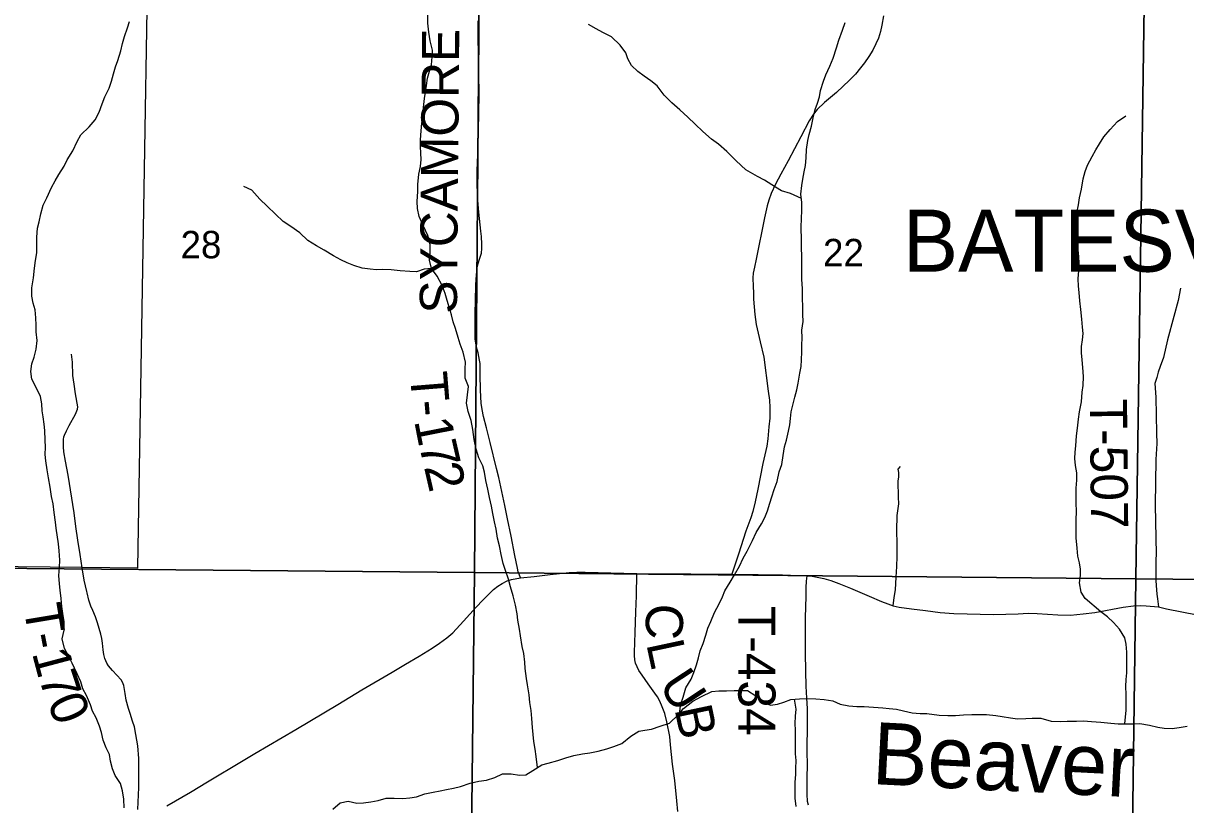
# Model space of a CAD drawing. Extents: x 0 to 191, y 0 to 55.
# Drawn here: x 185.647 to 187.422, y 51.096 to 52.289 of the extents above; entities that cross this region are included whole.
import ezdxf

# ---------------------------------------------------------------- set-up
doc = ezdxf.new("R2010")
doc.units = 0
for name, color, linetype in [('GM_X_Corporation', 7, 'Continuous'), ('GM_X_Corporation_Text', 7, 'Continuous'), ('GM_X_County_Road', 7, 'Continuous'), ('GM_X_Minor_River', 7, 'Continuous'), ('GM_X_Minor_River_Text', 7, 'Continuous'), ('GM_X_Section_Text', 7, 'Continuous'), ('GM_X_State_Route', 7, 'Continuous'), ('GM_X_Township_Road', 7, 'Continuous'), ('GM_X_Township_Road_Text', 7, 'Continuous')]:
    doc.layers.add(name, color=color, linetype=linetype)

msp = doc.modelspace()

# ---------------------------------------------------------------- linework, layer by layer
at = {"layer": 'GM_X_Corporation'}
for points in [[(184.8319, 50.3472), (184.8438, 50.7018), (184.8438, 50.7041), (184.8504, 51.1664), (184.8504, 51.1691), (184.8564, 51.468), (185.0493, 51.466), (185.0519, 51.466), (185.737, 51.4587), (185.8223, 51.4579), (185.8471, 52.9493), (185.8472, 52.953), (185.8634, 53.9305), (185.8653, 54.0182), (185.8655, 54.0321), (185.8681, 54.1568), (185.8476, 54.1564), (184.4129, 54.1665), (184.4114, 53.9192), (184.1701, 53.923), (184.1701, 49.9388)], [(184.8319, 50.3472), (184.8438, 50.7018), (184.8438, 50.7041), (184.8504, 51.1664), (184.8504, 51.1691), (184.8564, 51.468), (185.0493, 51.466), (185.0519, 51.466), (185.737, 51.4587), (185.8223, 51.4579), (185.8471, 52.9493), (185.8472, 52.953), (185.8634, 53.9305), (185.8653, 54.0182), (185.8655, 54.0321), (185.8681, 54.1568), (185.9791, 54.1551), (186.7401, 54.1422), (186.7662, 54.1447), (187.3845, 54.1319), (187.4205, 54.1315), (187.8766, 54.1257)]]:
    msp.add_lwpolyline(points, dxfattribs=at)
for points in [[(185.3319, 52.4794), (186.3443, 52.462), (186.336, 51.4505), (185.31, 51.4601)], [(186.3443, 52.462), (187.3608, 52.4557), (187.3457, 51.441), (186.336, 51.4505)], [(187.3608, 52.4557), (188.3785, 52.4395), (188.3652, 51.4321), (187.3457, 51.441)], [(186.336, 51.4505), (186.3245, 50.4222), (185.2935, 50.4401), (185.31, 51.4601)], [(187.3457, 51.441), (187.3319, 50.4112), (186.3245, 50.4222), (186.336, 51.4505)], [(188.3652, 51.4321), (188.3474, 50.3984), (187.3319, 50.4112), (187.3457, 51.441)]]:
    msp.add_lwpolyline(points, close=True, dxfattribs=at)
at = {"layer": 'GM_X_County_Road'}
msp.add_lwpolyline([(186.9603, 52.3005), (186.9582, 52.2862), (186.956, 52.2766), (186.9529, 52.2664), (186.949, 52.2576), (186.9441, 52.248), (186.9379, 52.2386), (186.9314, 52.2289), (186.9254, 52.2211), (186.9177, 52.2114), (186.9087, 52.2021), (186.8887, 52.1832), (186.8707, 52.1682), (186.8591, 52.1572), (186.8535, 52.1504), (186.8473, 52.1402), (186.8342, 52.1159), (186.8151, 52.079), (186.8038, 52.0589), (186.7955, 52.0437), (186.7888, 52.029), (186.7855, 52.0193), (186.7829, 52.0102), (186.7787, 51.992), (186.7662, 51.9291), (186.7636, 51.9166), (186.7616, 51.9076), (186.7609, 51.9007), (186.7615, 51.8875), (186.7619, 51.8774), (186.7622, 51.8679), (186.7642, 51.8447), (186.7662, 51.8294), (186.7692, 51.8161), (186.7724, 51.8026), (186.778, 51.7793), (186.7845, 51.7273), (186.7863, 51.714), (186.7869, 51.7027), (186.7868, 51.6864), (186.7856, 51.6729), (186.784, 51.6548), (186.7822, 51.6436), (186.7761, 51.6169), (186.7685, 51.5777), (186.7648, 51.5584), (186.7608, 51.5436), (186.7578, 51.5341), (186.7506, 51.5138), (186.739, 51.4787), (186.7289, 51.4482)], dxfattribs=at)
at = {"layer": 'GM_X_Minor_River'}
for points in [[(185.7142, 52.0806), (185.7229, 52.0943), (185.7297, 52.1084), (185.735, 52.1187), (185.7479, 52.1312), (185.757, 52.1415), (185.763, 52.1533), (185.7675, 52.1663), (185.7717, 52.1769), (185.7781, 52.1898), (185.7819, 52.2005), (185.7849, 52.2119), (185.7879, 52.2225), (185.7913, 52.2324), (185.7962, 52.2472), (185.7988, 52.2583), (185.8018, 52.2689), (185.8063, 52.2822), (185.8094, 52.2917)], [(186.4325, 51.1531), (186.4305, 51.1699), (186.4286, 51.1809), (186.4267, 51.1926), (186.4255, 51.2036), (186.4247, 51.2139), (186.4235, 51.2279), (186.4224, 51.2401), (186.4208, 51.2522), (186.4197, 51.264), (186.417, 51.2792), (186.4154, 51.289), (186.4135, 51.3042), (186.4131, 51.3141), (186.4115, 51.327), (186.4089, 51.3376), (186.4062, 51.3543), (186.4046, 51.3642), (186.4023, 51.3778), (186.4012, 51.3877), (186.3985, 51.401), (186.395, 51.415), (186.3912, 51.429), (186.3881, 51.4404), (186.3836, 51.4537), (186.3797, 51.4647), (186.377, 51.4783), (186.3744, 51.4916), (186.3713, 51.503), (186.369, 51.5167), (186.3667, 51.5281), (186.364, 51.5406), (186.3621, 51.552), (186.359, 51.5652), (186.3563, 51.5781), (186.3536, 51.5914), (186.3513, 51.6039), (186.3487, 51.6134), (186.3426, 51.6256), (186.3384, 51.6392), (186.3357, 51.6536), (186.3337, 51.6688), (186.331, 51.6828), (186.3265, 51.6965), (186.3241, 51.709), (186.3256, 51.7219), (186.3271, 51.7349), (186.3218, 51.7474), (186.3218, 51.7614), (186.3225, 51.7717), (186.3187, 51.7868), (186.3141, 51.7994), (186.3114, 51.8092), (186.3072, 51.8233), (186.3037, 51.8335), (186.3011, 51.8441), (186.298, 51.854), (186.2942, 51.8661), (186.2911, 51.8764), (186.2865, 51.8889), (186.2789, 51.9029), (186.2705, 51.9147), (186.2675, 51.9276), (186.2682, 51.9393), (186.2686, 51.9515), (186.2651, 51.9651), (186.2579, 51.9803), (186.2518, 51.9943), (186.2491, 52.0065), (186.2487, 52.0171), (186.2494, 52.0323), (186.2497, 52.0429), (186.2512, 52.0589), (186.2535, 52.0707), (186.2546, 52.0813), (186.2542, 52.0908), (186.2534, 52.1011), (186.2538, 52.1113), (186.2549, 52.125), (186.2556, 52.1368), (186.2575, 52.1489), (186.2582, 52.1607), (186.2597, 52.174), (186.2612, 52.1839), (186.263, 52.1941), (186.2645, 52.2052), (186.2672, 52.2162), (186.2702, 52.2257), (186.2713, 52.2378), (186.272, 52.2481), (186.2682, 52.2625), (186.2663, 52.2754), (186.2647, 52.2891), (186.2647, 52.3031)], [(186.8354, 52.0214), (186.8186, 52.0293), (186.8049, 52.0334), (186.7954, 52.0387), (186.7791, 52.0496), (186.7681, 52.0553), (186.7506, 52.0655), (186.7358, 52.0791), (186.7213, 52.0935), (186.7088, 52.1045), (186.6977, 52.1124), (186.6848, 52.1241), (186.673, 52.1351), (186.662, 52.1457), (186.6494, 52.1571), (186.6376, 52.1677), (186.6258, 52.1794), (186.6152, 52.1934), (186.6053, 52.2014), (186.595, 52.2085), (186.5855, 52.2153), (186.5756, 52.2244), (186.5703, 52.2347), (186.5669, 52.2441), (186.5585, 52.2559), (186.5452, 52.2684), (186.5319, 52.2752), (186.522, 52.2808), (186.5102, 52.2873)], [(186.6489, 51.2357), (186.6512, 51.2503), (186.6546, 51.2606), (186.6587, 51.2747), (186.667, 51.288), (186.6708, 51.2982), (186.6749, 51.31), (186.678, 51.3207), (186.6806, 51.3313), (186.6851, 51.3423), (186.6893, 51.3549), (186.6923, 51.3659), (186.6968, 51.3762), (186.7025, 51.3898), (186.7096, 51.4031), (186.7145, 51.4134), (186.7183, 51.4229), (186.7263, 51.4362), (186.7331, 51.4473), (186.7406, 51.4602), (186.7463, 51.4728), (186.7523, 51.4834), (186.7603, 51.4994), (186.7659, 51.5119), (186.7742, 51.5252), (186.7792, 51.5347), (186.7833, 51.545), (186.7871, 51.5564), (186.7901, 51.5663), (186.7935, 51.5773), (186.798, 51.5895), (186.8014, 51.6043), (186.8052, 51.6157), (186.8074, 51.6294), (186.8093, 51.6427), (186.8123, 51.6526), (186.8157, 51.6666), (186.8175, 51.6761), (186.8183, 51.6856), (186.8198, 51.6959), (186.822, 51.7061), (186.8254, 51.7183), (186.828, 51.7297), (186.8303, 51.7399), (186.8329, 51.7548), (186.8348, 51.7654), (186.8351, 51.7753), (186.8359, 51.7874), (186.8358, 51.7977), (186.8362, 51.8091), (186.8358, 51.8208), (186.8377, 51.8338), (186.8376, 51.8444), (186.8372, 51.8573), (186.8368, 51.8687), (186.8368, 51.8835), (186.836, 51.8983), (186.8356, 51.912), (186.8359, 51.9219), (186.8359, 51.9336), (186.8355, 51.9462), (186.8351, 51.9575), (186.835, 51.9784), (186.8354, 51.9906), (186.8357, 52.0039), (186.8361, 52.0157), (186.8345, 52.0282), (186.8356, 52.0415), (186.8375, 52.051), (186.8394, 52.0624), (186.8416, 52.0719), (186.8424, 52.0836), (186.8431, 52.0962), (186.845, 52.1099), (186.8468, 52.1194), (186.8506, 52.1319), (186.8532, 52.1448), (186.8562, 52.1574), (186.86, 52.1673), (186.8626, 52.1768), (186.8645, 52.1863), (186.869, 52.2007), (186.8724, 52.2102), (186.8785, 52.2235), (186.8838, 52.2357), (186.8886, 52.2517), (186.8924, 52.2631), (186.8981, 52.2783), (186.9018, 52.2901)], [(187.3292, 51.2196), (187.3312, 51.2408), (187.3312, 51.2647), (187.3307, 51.2769), (187.3311, 51.2875), (187.3318, 51.2977), (187.3318, 51.3088), (187.3322, 51.3194), (187.3321, 51.3293), (187.331, 51.3414), (187.3291, 51.3509), (187.3211, 51.3641), (187.3119, 51.3744), (187.3024, 51.3831), (187.2925, 51.3906), (187.2682, 51.4111), (187.2625, 51.4205), (187.2598, 51.4349), (187.2613, 51.446), (187.2613, 51.4558), (187.2597, 51.4653), (187.2571, 51.4756), (187.2563, 51.4877), (187.2547, 51.5036), (187.2547, 51.531), (187.255, 51.5439), (187.2546, 51.5572), (187.2546, 51.5686), (187.2549, 51.5796), (187.2556, 51.5917), (187.2556, 51.6031), (187.2537, 51.6141), (187.2529, 51.6248), (187.2533, 51.6346), (187.254, 51.6441), (187.2551, 51.6593), (187.2566, 51.6711), (187.2581, 51.6848), (187.26, 51.6958), (187.2626, 51.7114), (187.2641, 51.7258), (187.2652, 51.7364), (187.2659, 51.7501), (187.2647, 51.7638), (187.264, 51.7755), (187.2628, 51.7862), (187.2628, 51.7956), (187.2646, 51.8059), (187.2654, 51.8154), (187.2646, 51.8253), (187.2634, 51.8374), (187.2619, 51.8522), (187.2603, 51.8655), (187.2592, 51.878), (187.2584, 51.8879), (187.2576, 51.8989), (187.2587, 51.9118), (187.2594, 51.9225), (187.2586, 51.9331), (187.2575, 51.9426), (187.2563, 51.9547), (187.2548, 51.9676), (187.2536, 51.9786), (187.254, 51.9893), (187.2555, 51.9995), (187.2581, 52.0117), (187.2599, 52.0227), (187.2626, 52.036), (187.2656, 52.0516), (187.2686, 52.0626), (187.272, 52.0725), (187.2792, 52.0858), (187.2848, 52.0957), (187.2901, 52.1052), (187.2969, 52.1155), (187.3064, 52.1269), (187.3177, 52.1391), (187.3306, 52.1479)], [(185.8012, 51.0914), (185.8007, 51.1047), (185.7988, 51.1176), (185.7958, 51.1286), (185.7874, 51.1411), (185.7832, 51.1509), (185.7805, 51.1627), (185.7786, 51.173), (185.7736, 51.1832), (185.769, 51.1946), (185.7664, 51.2067), (185.7637, 51.2162), (185.7583, 51.2291), (185.753, 51.2389), (185.7496, 51.2488), (185.7435, 51.2632), (185.7381, 51.2734), (185.7351, 51.2837), (185.7297, 51.2962), (185.7217, 51.3121), (185.7175, 51.3216), (185.7103, 51.3345), (185.7068, 51.3496), (185.7095, 51.3629), (185.7094, 51.3762), (185.7075, 51.3884), (185.706, 51.3986), (185.7052, 51.4111), (185.7036, 51.424), (185.7025, 51.4335), (185.7017, 51.4461), (185.7024, 51.4582), (185.7028, 51.4696), (185.702, 51.4836), (185.7008, 51.4943), (185.6974, 51.5182), (185.6962, 51.5277), (185.6946, 51.5425), (185.6927, 51.5554), (185.6904, 51.5668), (185.6881, 51.5812), (185.6858, 51.5952), (185.6839, 51.6077), (185.6816, 51.621), (185.6808, 51.6309), (185.6811, 51.6423), (185.6807, 51.6529), (185.6803, 51.6677), (185.6791, 51.6772), (185.6776, 51.6882), (185.6761, 51.6977), (185.6753, 51.708), (185.6737, 51.7193), (185.6676, 51.7322), (185.6604, 51.7459), (185.6589, 51.7573), (185.66, 51.7694), (185.6637, 51.7793), (185.6667, 51.7915), (185.6686, 51.8051), (185.6671, 51.818), (185.667, 51.8283), (185.6666, 51.8393), (185.6651, 51.8518), (185.6624, 51.8617), (185.6605, 51.8723), (185.6601, 51.8852), (185.6627, 51.9004), (185.6642, 51.9153), (185.666, 51.927), (185.6679, 51.9388), (185.6679, 51.9624), (185.669, 51.9764), (185.6712, 51.9859), (185.6738, 51.9981), (185.6776, 52.0114), (185.6829, 52.0228), (185.6901, 52.0384), (185.6957, 52.0487), (185.7014, 52.0582), (185.7097, 52.0711), (185.7142, 52.0806)], [(186.2705, 51.9147), (186.2595, 51.9135), (186.2474, 51.9096), (186.2372, 51.9104), (186.2227, 51.9111), (186.2091, 51.9129), (186.1962, 51.9133), (186.1863, 51.9129), (186.1768, 51.9136), (186.1647, 51.9151), (186.1518, 51.9192), (186.1419, 51.9233), (186.132, 51.9282), (186.1206, 51.9343), (186.1065, 51.9426), (186.0948, 51.9494), (186.0818, 51.9577), (186.0693, 51.9694), (186.0556, 51.9789), (186.0442, 51.9864), (186.0324, 51.9978), (186.0195, 52.0099), (186.0085, 52.0205), (185.9959, 52.0345), (185.9841, 52.0401)], [(186.1199, 51.0895), (186.1309, 51.0994), (186.1434, 51.1017), (186.1567, 51.0987), (186.1666, 51.0991), (186.1776, 51.1007), (186.1889, 51.1026), (186.2014, 51.1061), (186.2132, 51.1065), (186.2269, 51.1058), (186.2375, 51.1066), (186.2477, 51.1085), (186.2602, 51.1127), (186.2728, 51.1154), (186.2838, 51.1174), (186.2932, 51.1197), (186.3039, 51.1216), (186.3145, 51.1239), (186.3293, 51.1293), (186.3425, 51.1324), (186.3543, 51.1339), (186.3672, 51.1378), (186.379, 51.1435), (186.3919, 51.1432), (186.4048, 51.1413), (186.4146, 51.1417), (186.4252, 51.1486), (186.4389, 51.157), (186.4484, 51.1597), (186.4631, 51.1639), (186.4753, 51.1681), (186.4878, 51.1712), (186.5011, 51.1739), (186.5121, 51.1755), (186.525, 51.1782), (186.5379, 51.1816), (186.5489, 51.1851), (186.561, 51.1897), (186.575, 51.2011), (186.5868, 51.2084), (186.5962, 51.2103), (186.6061, 51.2115), (186.6198, 51.2161), (186.6338, 51.221), (186.647, 51.2336), (186.6554, 51.2431), (186.6694, 51.2546), (186.6826, 51.2614), (186.6982, 51.2691), (186.7092, 51.2703), (186.7206, 51.2703), (186.7323, 51.2707), (186.7422, 51.2708), (186.7528, 51.2704), (186.7657, 51.2625), (186.7775, 51.253), (186.7878, 51.2481), (186.7988, 51.2497), (186.8083, 51.2528), (186.8189, 51.257), (186.8325, 51.2581), (186.8439, 51.2586), (186.8572, 51.2579), (186.8701, 51.2571), (186.8834, 51.2549), (186.8944, 51.25), (186.9077, 51.2474), (186.9198, 51.2463), (186.9312, 51.2463), (186.9453, 51.2452), (186.9597, 51.2441), (186.9692, 51.2434), (186.9806, 51.2419), (186.9912, 51.2397)], [(186.8244, 51.2574), (186.8265, 51.2422), (186.8258, 51.2316), (186.8254, 51.2202), (186.8258, 51.2103), (186.8255, 51.197), (186.8255, 51.1875), (186.8259, 51.1742), (186.8267, 51.1636), (186.8263, 51.1518), (186.826, 51.1423), (186.8252, 51.1309), (186.8253, 51.1063), (186.8268, 51.0934)], [(186.9912, 51.2397), (187.0041, 51.2367), (187.0163, 51.2356), (187.0265, 51.2353), (187.0455, 51.233), (187.0588, 51.2323), (187.0705, 51.2324), (187.0827, 51.2335), (187.0952, 51.234), (187.1176, 51.234), (187.132, 51.2326), (187.1419, 51.2311), (187.1544, 51.2288), (187.165, 51.2274), (187.1776, 51.2278), (187.1874, 51.2286), (187.2007, 51.2282), (187.2163, 51.2237), (187.2307, 51.2234), (187.2409, 51.2238), (187.255, 51.2238), (187.266, 51.2243), (187.2781, 51.2235), (187.2925, 51.2224), (187.3077, 51.221), (187.3187, 51.2199), (187.3282, 51.2195), (187.3415, 51.2199), (187.3521, 51.2204), (187.3666, 51.2178), (187.3795, 51.2148), (187.3893, 51.2133), (187.4011, 51.2125), (187.4121, 51.2141), (187.4242, 51.216)]]:
    msp.add_lwpolyline(points, dxfattribs=at)
at = {"layer": 'GM_X_State_Route'}
msp.add_lwpolyline([(185.8662, 51.0947), (185.9026, 51.1156), (185.9283, 51.1311), (185.983, 51.1639), (186.0007, 51.1743), (186.0635, 51.2113), (186.1273, 51.2493), (186.1643, 51.2714), (186.2105, 51.2987), (186.2309, 51.3108), (186.2515, 51.3229), (186.2713, 51.3351), (186.2829, 51.3427), (186.2941, 51.3508), (186.303, 51.3587), (186.3195, 51.3767), (186.3387, 51.3979), (186.3488, 51.4084), (186.3652, 51.4248), (186.3715, 51.4298), (186.3784, 51.4341), (186.3859, 51.438), (186.3924, 51.4399), (186.4062, 51.4427), (186.4274, 51.4447), (186.4515, 51.4475), (186.4805, 51.4507), (186.4925, 51.4515), (186.505, 51.4514), (186.5839, 51.4494), (186.6664, 51.4485), (186.7289, 51.4482), (186.769, 51.4478), (186.8064, 51.4473), (186.8436, 51.4458), (186.8515, 51.4449), (186.8593, 51.4438), (186.8695, 51.4417), (186.8799, 51.4386), (186.8925, 51.434), (186.91, 51.427), (186.9387, 51.4144), (186.9575, 51.4065), (186.9671, 51.4028), (186.9754, 51.4), (186.9846, 51.3979), (187.0034, 51.3953), (187.0249, 51.3925), (187.047, 51.3896), (187.0679, 51.3882), (187.1283, 51.3864), (187.1661, 51.3877), (187.1814, 51.3885), (187.1952, 51.3882), (187.2269, 51.3859), (187.2462, 51.3857), (187.2652, 51.3876), (187.283, 51.3899), (187.3264, 51.3977), (187.3421, 51.3998), (187.3525, 51.4003), (187.3616, 51.3999), (187.3803, 51.3985), (187.3928, 51.3953), (187.4392, 51.3861)], dxfattribs=at)
at = {"layer": 'GM_X_Township_Road'}
for points in [[(186.4062, 51.4427), (186.4043, 51.4481), (186.403, 51.452), (186.4018, 51.4575), (186.3978, 51.4768), (186.3922, 51.5064), (186.3867, 51.5328), (186.3824, 51.553), (186.3733, 51.596), (186.3696, 51.6096), (186.3598, 51.6492), (186.3546, 51.6715), (186.35, 51.6889), (186.3478, 51.6993), (186.3463, 51.709), (186.3451, 51.7292), (186.3449, 51.7532), (186.3446, 51.7651), (186.3445, 51.7699), (186.3435, 51.7749), (186.3416, 51.7858), (186.3394, 51.7947), (186.3373, 51.8069), (186.337, 51.8164), (186.337, 51.8281), (186.3369, 51.847), (186.3377, 51.8655), (186.3382, 51.8893), (186.3385, 51.8985), (186.3389, 51.9048), (186.3396, 51.9106), (186.3404, 51.9159), (186.3419, 51.9226), (186.3439, 51.9289), (186.3467, 51.938), (186.3473, 51.9452), (186.3475, 51.9518), (186.3468, 51.9638), (186.3459, 51.9717), (186.3428, 52.0007), (186.3406, 52.0248), (186.3403, 52.0483), (186.3402, 52.0642), (186.3418, 52.1007), (186.3425, 52.1516), (186.343, 52.1808), (186.3428, 52.2123), (186.3422, 52.2439), (186.3416, 52.266), (186.3416, 52.2778), (186.3415, 52.293)], [(187.4142, 51.8847), (187.4102, 51.8658), (187.4039, 51.8416), (187.3941, 51.806), (187.3882, 51.779), (187.3827, 51.765), (187.38, 51.7567), (187.3776, 51.7484), (187.3749, 51.7393), (187.3762, 51.7183), (187.3772, 51.6636), (187.3779, 51.6475), (187.3765, 51.6232), (187.3754, 51.5536), (187.3766, 51.4786), (187.3765, 51.4699), (187.3761, 51.4485), (187.3763, 51.4383), (187.3769, 51.4308), (187.3779, 51.4179), (187.3787, 51.4105), (187.3803, 51.3985)], [(185.7442, 51.4217), (185.7404, 51.4388), (185.7372, 51.4581), (185.7342, 51.4782), (185.7305, 51.5001), (185.7276, 51.5211), (185.7247, 51.5419), (185.7158, 51.5991), (185.7116, 51.6209), (185.7093, 51.635), (185.7087, 51.6426), (185.7084, 51.6486), (185.7085, 51.6539), (185.7091, 51.6576), (185.7099, 51.6606), (185.7131, 51.6671), (185.7174, 51.6749), (185.7271, 51.6923), (185.7292, 51.6976), (185.7299, 51.7002), (185.7304, 51.7037), (185.7271, 51.7232), (185.7247, 51.7383), (185.723, 51.7514), (185.7222, 51.7716), (185.721, 51.7842)], [(186.9754, 51.4), (186.977, 51.4127), (186.9787, 51.4241), (186.98, 51.4436), (186.9807, 51.46), (186.9814, 51.475), (186.9812, 51.4943), (186.9807, 51.5146), (186.9812, 51.5379), (186.9839, 51.5557), (186.9836, 51.5658), (186.9828, 51.59), (186.9841, 51.597), (186.9839, 51.6032), (186.9827, 51.6083), (186.9864, 51.6123)], [(186.6464, 51.0857), (186.645, 51.102), (186.642, 51.1333), (186.6385, 51.1581), (186.6354, 51.1879), (186.6343, 51.2004), (186.6298, 51.2226), (186.6265, 51.2353), (186.6218, 51.2481), (186.6186, 51.2553), (186.6153, 51.2608), (186.6114, 51.2668), (186.6011, 51.281), (186.592, 51.2942), (186.5872, 51.3014), (186.5842, 51.3069), (186.582, 51.3125), (186.5809, 51.3176), (186.5803, 51.324), (186.5805, 51.3285), (186.5816, 51.3594), (186.5825, 51.3906), (186.5833, 51.4152), (186.5839, 51.4494)], [(186.8436, 51.4458), (186.8427, 51.4376), (186.8419, 51.4277), (186.8418, 51.4143), (186.841, 51.3822), (186.8407, 51.3587), (186.8408, 51.3444), (186.8407, 51.3279), (186.8412, 51.3002), (186.8419, 51.2774), (186.8432, 51.259), (186.8441, 51.2432), (186.844, 51.2197), (186.8437, 51.1783), (186.8442, 51.156), (186.8437, 51.1381), (186.8433, 51.1211), (186.8434, 51.1119), (186.8441, 51.1017), (186.8453, 51.0959)], [(185.8223, 51.0892), (185.8234, 51.1225), (185.8236, 51.1439), (185.8236, 51.1669), (185.822, 51.1862), (185.8192, 51.2037), (185.8169, 51.2152), (185.8142, 51.224), (185.8104, 51.2354), (185.808, 51.243), (185.8044, 51.2558), (185.8028, 51.2659), (185.8005, 51.2781), (185.7986, 51.2834), (185.7967, 51.287), (185.7832, 51.3014), (185.7775, 51.3081), (185.7747, 51.3126), (185.7716, 51.3193), (185.7702, 51.3256), (185.7691, 51.3328), (185.7683, 51.3431), (185.7669, 51.3502), (185.7657, 51.3564), (185.7633, 51.3651), (185.7607, 51.374), (185.7574, 51.383), (185.7532, 51.3928), (185.7505, 51.3995), (185.7473, 51.4085), (185.7447, 51.4196), (185.7442, 51.4217)]]:
    msp.add_lwpolyline(points, dxfattribs=at)

# ---------------------------------------------------------------- texts
at = {"layer": 'GM_X_Corporation_Text'}
msp.add_text('BATESVILLE', height=0.0947, rotation=0, dxfattribs=at).set_placement((186.99, 51.9099))
at = {"layer": 'GM_X_Minor_River_Text'}
msp.add_text('Beaver', height=0.0947, rotation=357.0891, dxfattribs=at).set_placement((186.9416, 51.1279))
at = {"layer": 'GM_X_Section_Text'}
for s, p in [('28', (185.8874, 51.9303)), ('22', (186.8682, 51.9181))]:
    msp.add_text(s, height=0.04186, rotation=0, dxfattribs=at).set_placement(p)
at = {"layer": 'GM_X_Township_Road_Text'}
for s, height, rotation, p in [('SYCAMORE', 0.05682, 89.5094, (186.3092, 51.8456)), ('T', 0.0568, 274.6291, (186.2374, 51.755)), ('-', 0.0568, 275.0175, (186.2408, 51.7122)), ('T-507', 0.05682, 270.5407, (187.2755, 51.7159)), ('1', 0.0568, 281.1453, (186.2438, 51.6824)), ('7', 0.0568, 282.8759, (186.251, 51.6463)), ('2', 0.0568, 282.9556, (186.2588, 51.6121)), ('T', 0.0568, 279.406, (185.6475, 51.3985)), ('C', 0.0568, 267.474, (186.5989, 51.4042)), ('T-434', 0.05682, 270.0032, (186.7388, 51.4)), ('-', 0.0568, 281.049, (185.6548, 51.3549)), ('L', 0.0568, 282.0978, (186.5982, 51.3419)), ('1', 0.0568, 284.8367, (185.6602, 51.328)), ('7', 0.0568, 288.2626, (185.6702, 51.2906)), ('U', 0.0568, 303.4081, (186.6159, 51.2792)), ('0', 0.0568, 292.5189, (185.6828, 51.253)), ('B', 0.0568, 281.9315, (186.6413, 51.2426))]:
    msp.add_text(s, height=height, rotation=rotation, dxfattribs=at).set_placement(p)

doc.saveas('drawing.dxf')
